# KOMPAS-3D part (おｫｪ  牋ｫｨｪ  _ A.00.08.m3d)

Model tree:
1. Эскиз:1
2. Операция выдавливания:1
     Расстояние 1 = 35; Расстояние 2 = 7
3. Эскиз:2
4. Операция выдавливания:2
     Расстояние 1 = 3
5. Эскиз:3
6. Операция выдавливания:3
     Расстояние 1 = 50
7. Скругление:1
     Радиус = 6
8. Скругление:2
     Радиус = 3
9. Скругление:3
     Радиус = 15
10. Эскиз:4
11. Вырезать элемент выдавливания:1
     Расстояние 1 = 78
12. Эскиз:7
13. Вырезать элемент выдавливания:4  (labels: A.00.08)
     Расстояние 2 = 10
